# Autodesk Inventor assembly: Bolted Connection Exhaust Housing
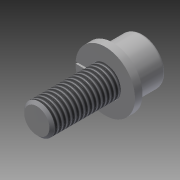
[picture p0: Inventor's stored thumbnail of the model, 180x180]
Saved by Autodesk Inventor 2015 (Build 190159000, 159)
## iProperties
Created: 2007-02
Part Number: Bolted Connection Exhaust Housing
Document SubType Name: Assembly
Designer: Autodesk, Inc.
Mass: 7.97732 g
Surface Area: 9.80493 cm^2
Volume: 1.01493 cm^3
Density: 7.86 g/cm^3
ClientObjectVersion: 1
Author: Autodesk, Inc.
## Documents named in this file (3)
- C:\Users\Public\Documents\Autodesk\Inventor 2015\Samples\Models\Assemblies\Blower\Exhaust\Design Accelerator\Bolted Connection Motor Mount 21.iam
- C:\Users\Public\Documents\Autodesk\Inventor 2015\Samples\Standard Parts\en-US\ANSI B18.21.1\ANSI B18.21.1 - 0.25.ipt
- C:\Users\Public\Documents\Autodesk\Inventor 2015\Samples\Standard Parts\en-US\ANSI B18.3(13)\ANSI B18.3 - 1_4-28 UNF - 0.625(22).ipt
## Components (2 placed, 2 different names)
1. ANSI B18.21.1 - 0.25:1
2. ANSI B18.3 - 1/4-28 UNF - 0.625:2
